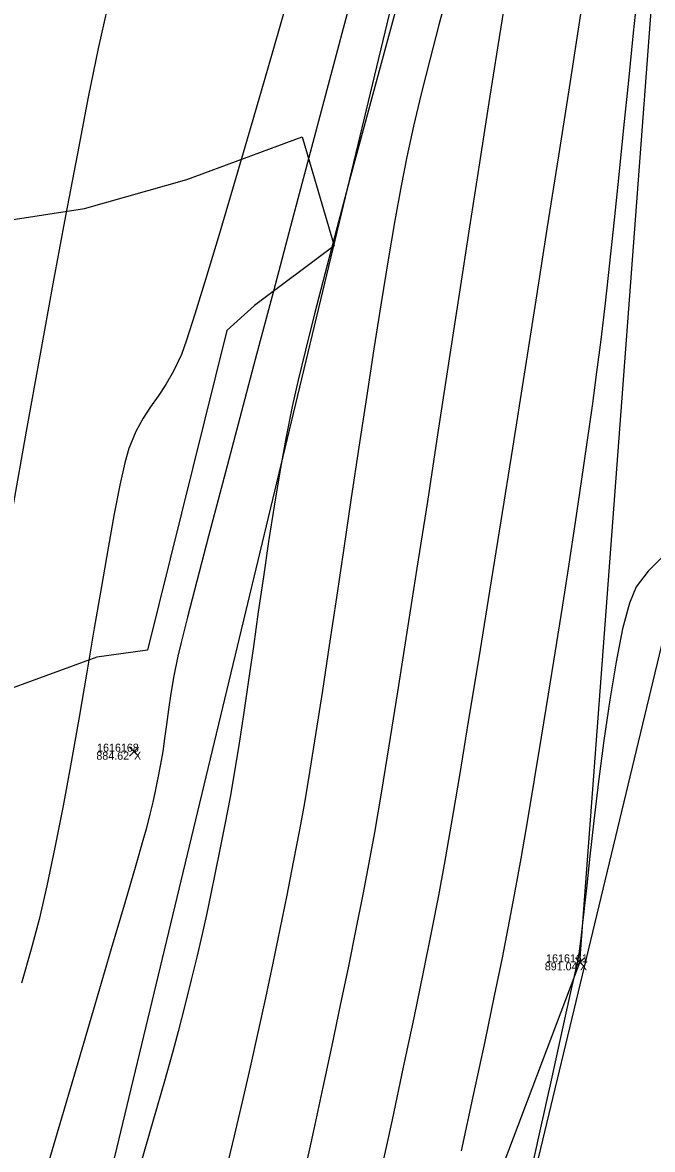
# Model space of a CAD drawing. Extents: x 1957117 to 1971063, y 701601 to 715861.
# Drawn here: x 1963262.79 to 1963290.32, y 705884.08 to 705933.37 of the extents above; entities that cross this region are included whole.
import ezdxf

# ---------------------------------------------------------------- set-up
doc = ezdxf.new("R2010")
doc.units = 0
for name, color, linetype in [('AP_X_Lights', 7, 'Continuous'), ('DT_X_Break_Line', 7, 'Continuous'), ('DT_X_Contour_Major', 7, 'Continuous'), ('DT_X_Contour_Minor', 7, 'Continuous'), ('GE_X_CL_20', 7, 'Continuous'), ('HY_X_Water_Edge', 7, 'Continuous'), ('PV_P_Shoulder', 7, 'Continuous'), ('RS_Raster1', 7, 'Continuous'), ('RW_X_Esmt_RR', 7, 'Continuous'), ('SC_Scratch1', 7, 'Continuous'), ('SC_Shading5', 7, 'Continuous'), ('VG_X_Tree_Line_Rt', 7, 'Continuous')]:
    doc.layers.add(name, color=color, linetype=linetype)

msp = doc.modelspace()

# ---------------------------------------------------------------- linework, layer by layer
at = {"layer": 'AP_X_Lights'}
for p, q in [((1963267.464, 705901.283), (1963267.852, 705901.673)), ((1963267.464, 705901.673), (1963267.852, 705901.283)), ((1963286.959, 705892.069), (1963287.347, 705892.459)), ((1963286.959, 705892.459), (1963287.347, 705892.069))]:
    msp.add_line(p, q, dxfattribs=at)
at = {"layer": 'DT_X_Break_Line'}
msp.add_lwpolyline([(1963248.355, 705747.376), (1963261.829, 705795.923), (1963267.581, 705840.559), (1963287.153, 705892.264), (1963291.083, 705944.763), (1963301.574, 705996.211), (1963311.528, 706039.027), (1963334.717, 706086.75), (1963331.957, 706106.508), (1963348.786, 706182.796), (1963365.664, 706223.934), (1963373.462, 706281.461), (1963387.853, 706330.217), (1963397.264, 706379.501), (1963407.696, 706427.592), (1963426.755, 706477.16), (1963442.136, 706524.014), (1963446.007, 706569.971), (1963489.391, 706666.839), (1963500.526, 706701.536)], dxfattribs=at)
at = {"layer": 'DT_X_Contour_Major'}
for points in [[(1963289.692, 705934.967), (1963289.482, 705932.914), (1963289.271, 705930.834), (1963289.062, 705928.756), (1963288.854, 705926.712), (1963288.649, 705924.732), (1963288.449, 705922.847), (1963288.253, 705921.089), (1963288.064, 705919.486), (1963287.882, 705918.071), (1963287.679, 705916.598), (1963287.452, 705915.001), (1963287.205, 705913.302), (1963286.941, 705911.52), (1963286.662, 705909.677), (1963286.372, 705907.794), (1963286.073, 705905.89), (1963285.769, 705903.988), (1963285.463, 705902.107), (1963285.157, 705900.269), (1963284.856, 705898.493), (1963284.561, 705896.801), (1963284.276, 705895.214), (1963284.004, 705893.753), (1963283.749, 705892.463), (1963283.407, 705890.796), (1963282.987, 705888.799), (1963282.501, 705886.525), (1963281.961, 705884.024)], [(1963289.692, 705934.967), (1963289.482, 705932.914), (1963289.271, 705930.834), (1963289.062, 705928.756), (1963288.854, 705926.712), (1963288.649, 705924.732), (1963288.449, 705922.847), (1963288.253, 705921.089), (1963288.064, 705919.486), (1963287.882, 705918.071), (1963287.679, 705916.598), (1963287.452, 705915.001), (1963287.205, 705913.302), (1963286.941, 705911.52), (1963286.662, 705909.677), (1963286.372, 705907.794), (1963286.073, 705905.89), (1963285.769, 705903.988), (1963285.463, 705902.107), (1963285.157, 705900.269), (1963284.856, 705898.493), (1963284.561, 705896.801), (1963284.276, 705895.214), (1963284.004, 705893.753), (1963283.749, 705892.463), (1963283.407, 705890.796), (1963282.987, 705888.799), (1963282.501, 705886.525), (1963281.961, 705884.024)], [(1963277.092, 705934.198), (1963276.263, 705931.077), (1963275.421, 705927.903), (1963274.579, 705924.731), (1963273.753, 705921.62), (1963272.958, 705918.624), (1963272.211, 705915.801), (1963271.526, 705913.208), (1963270.918, 705910.899), (1963270.404, 705908.933), (1963269.997, 705907.365), (1963269.715, 705906.252), (1963269.571, 705905.65), (1963269.404, 705904.802), (1963269.273, 705904.028), (1963269.167, 705903.32), (1963269.078, 705902.666), (1963268.996, 705902.056), (1963268.913, 705901.481), (1963268.818, 705900.93), (1963268.691, 705900.269), (1963268.586, 705899.745), (1963268.481, 705899.268), (1963268.357, 705898.748), (1963268.191, 705898.096), (1963268.05, 705897.597), (1963267.737, 705896.516), (1963267.269, 705894.915), (1963266.665, 705892.857), (1963265.944, 705890.404), (1963265.125, 705887.618), (1963264.225, 705884.563), (1963263.263, 705881.3)], [(1963277.092, 705934.198), (1963276.263, 705931.077), (1963275.421, 705927.903), (1963274.579, 705924.731), (1963273.753, 705921.62), (1963272.958, 705918.624), (1963272.211, 705915.801), (1963271.526, 705913.208), (1963270.918, 705910.899), (1963270.404, 705908.933), (1963269.997, 705907.365), (1963269.715, 705906.252), (1963269.571, 705905.65), (1963269.404, 705904.802), (1963269.273, 705904.028), (1963269.167, 705903.32), (1963269.078, 705902.666), (1963268.996, 705902.056), (1963268.913, 705901.481), (1963268.818, 705900.93), (1963268.691, 705900.269), (1963268.586, 705899.745), (1963268.481, 705899.268), (1963268.357, 705898.748), (1963268.191, 705898.096), (1963268.05, 705897.597), (1963267.737, 705896.516), (1963267.269, 705894.915), (1963266.665, 705892.857), (1963265.944, 705890.404), (1963265.125, 705887.618), (1963264.225, 705884.563), (1963263.263, 705881.3)]]:
    msp.add_lwpolyline(points, dxfattribs=at)
at = {"layer": 'DT_X_Contour_Minor'}
for points in [[(1963287.494, 705935.797), (1963287.104, 705933.274), (1963286.674, 705930.505), (1963286.212, 705927.542), (1963285.726, 705924.433), (1963285.223, 705921.231), (1963284.712, 705917.986), (1963284.199, 705914.749), (1963283.692, 705911.569), (1963283.2, 705908.498), (1963282.729, 705905.586), (1963282.287, 705902.884), (1963281.883, 705900.443), (1963281.522, 705898.313), (1963281.215, 705896.544), (1963280.966, 705895.188), (1963280.664, 705893.637), (1963280.301, 705891.842), (1963279.887, 705889.842), (1963279.431, 705887.676), (1963278.94, 705885.381), (1963278.423, 705882.996)], [(1963287.494, 705935.797), (1963287.104, 705933.274), (1963286.674, 705930.505), (1963286.212, 705927.542), (1963285.726, 705924.433), (1963285.223, 705921.231), (1963284.712, 705917.986), (1963284.199, 705914.749), (1963283.692, 705911.569), (1963283.2, 705908.498), (1963282.729, 705905.586), (1963282.287, 705902.884), (1963281.883, 705900.443), (1963281.522, 705898.313), (1963281.215, 705896.544), (1963280.966, 705895.188), (1963280.664, 705893.637), (1963280.301, 705891.842), (1963279.887, 705889.842), (1963279.431, 705887.676), (1963278.94, 705885.381), (1963278.423, 705882.996)], [(1963279.535, 705935.557), (1963278.908, 705933.245), (1963278.285, 705930.94), (1963277.673, 705928.672), (1963277.085, 705926.475), (1963276.528, 705924.38), (1963276.014, 705922.419), (1963275.552, 705920.626), (1963275.152, 705919.032), (1963274.825, 705917.669), (1963274.579, 705916.57), (1963274.301, 705915.177), (1963274.037, 705913.719), (1963273.785, 705912.213), (1963273.544, 705910.678), (1963273.314, 705909.131), (1963273.091, 705907.591), (1963272.876, 705906.076), (1963272.666, 705904.603), (1963272.461, 705903.19), (1963272.258, 705901.856), (1963272.057, 705900.618), (1963271.855, 705899.494), (1963271.625, 705898.289), (1963271.413, 705897.2), (1963271.213, 705896.199), (1963271.018, 705895.257), (1963270.822, 705894.345), (1963270.618, 705893.435), (1963270.399, 705892.498), (1963270.158, 705891.506), (1963269.89, 705890.43), (1963269.587, 705889.241), (1963269.349, 705888.359), (1963268.985, 705887.066), (1963268.509, 705885.408), (1963267.935, 705883.433)], [(1963279.535, 705935.557), (1963278.908, 705933.245), (1963278.285, 705930.94), (1963277.673, 705928.672), (1963277.085, 705926.475), (1963276.528, 705924.38), (1963276.014, 705922.419), (1963275.552, 705920.626), (1963275.152, 705919.032), (1963274.825, 705917.669), (1963274.579, 705916.57), (1963274.301, 705915.177), (1963274.037, 705913.719), (1963273.785, 705912.213), (1963273.544, 705910.678), (1963273.314, 705909.131), (1963273.091, 705907.591), (1963272.876, 705906.076), (1963272.666, 705904.603), (1963272.461, 705903.19), (1963272.258, 705901.856), (1963272.057, 705900.618), (1963271.855, 705899.494), (1963271.625, 705898.289), (1963271.413, 705897.2), (1963271.213, 705896.199), (1963271.018, 705895.257), (1963270.822, 705894.345), (1963270.618, 705893.435), (1963270.399, 705892.498), (1963270.158, 705891.506), (1963269.89, 705890.43), (1963269.587, 705889.241), (1963269.349, 705888.359), (1963268.985, 705887.066), (1963268.509, 705885.408), (1963267.935, 705883.433)], [(1963281.399, 705934.836), (1963280.982, 705933.268), (1963280.587, 705931.736), (1963280.218, 705930.255), (1963279.883, 705928.835), (1963279.587, 705927.491), (1963279.334, 705926.219), (1963279.06, 705924.709), (1963278.768, 705922.994), (1963278.462, 705921.11), (1963278.143, 705919.092), (1963277.818, 705916.975), (1963277.487, 705914.794), (1963277.156, 705912.584), (1963276.828, 705910.379), (1963276.505, 705908.216), (1963276.192, 705906.129), (1963275.893, 705904.152), (1963275.609, 705902.322), (1963275.346, 705900.673), (1963275.106, 705899.24), (1963274.892, 705898.059), (1963274.62, 705896.646), (1963274.333, 705895.197), (1963274.033, 705893.72), (1963273.722, 705892.222), (1963273.4, 705890.71), (1963273.07, 705889.193), (1963272.732, 705887.677), (1963272.389, 705886.171), (1963272.04, 705884.681), (1963271.689, 705883.215)], [(1963281.399, 705934.836), (1963280.982, 705933.268), (1963280.587, 705931.736), (1963280.218, 705930.255), (1963279.883, 705928.835), (1963279.587, 705927.491), (1963279.334, 705926.219), (1963279.06, 705924.709), (1963278.768, 705922.994), (1963278.462, 705921.11), (1963278.143, 705919.092), (1963277.818, 705916.975), (1963277.487, 705914.794), (1963277.156, 705912.584), (1963276.828, 705910.379), (1963276.505, 705908.216), (1963276.192, 705906.129), (1963275.893, 705904.152), (1963275.609, 705902.322), (1963275.346, 705900.673), (1963275.106, 705899.24), (1963274.892, 705898.059), (1963274.62, 705896.646), (1963274.333, 705895.197), (1963274.033, 705893.72), (1963273.722, 705892.222), (1963273.4, 705890.71), (1963273.07, 705889.193), (1963272.732, 705887.677), (1963272.389, 705886.171), (1963272.04, 705884.681), (1963271.689, 705883.215)], [(1963283.89, 705934.359), (1963283.552, 705932.255), (1963283.174, 705929.864), (1963282.764, 705927.237), (1963282.33, 705924.428), (1963281.876, 705921.49), (1963281.413, 705918.475), (1963280.945, 705915.436), (1963280.481, 705912.427), (1963280.027, 705909.5), (1963279.591, 705906.707), (1963279.18, 705904.103), (1963278.802, 705901.74), (1963278.462, 705899.67), (1963278.169, 705897.947), (1963277.929, 705896.623), (1963277.66, 705895.229), (1963277.358, 705893.712), (1963277.029, 705892.093), (1963276.676, 705890.39), (1963276.303, 705888.622), (1963275.915, 705886.808), (1963275.515, 705884.967), (1963275.107, 705883.118)], [(1963283.89, 705934.359), (1963283.552, 705932.255), (1963283.174, 705929.864), (1963282.764, 705927.237), (1963282.33, 705924.428), (1963281.876, 705921.49), (1963281.413, 705918.475), (1963280.945, 705915.436), (1963280.481, 705912.427), (1963280.027, 705909.5), (1963279.591, 705906.707), (1963279.18, 705904.103), (1963278.802, 705901.74), (1963278.462, 705899.67), (1963278.169, 705897.947), (1963277.929, 705896.623), (1963277.66, 705895.229), (1963277.358, 705893.712), (1963277.029, 705892.093), (1963276.676, 705890.39), (1963276.303, 705888.622), (1963275.915, 705886.808), (1963275.515, 705884.967), (1963275.107, 705883.118)], [(1963266.479, 705933.988), (1963266.096, 705932.231), (1963265.661, 705930.1), (1963265.181, 705927.644), (1963264.663, 705924.908), (1963264.113, 705921.939), (1963263.538, 705918.785), (1963262.945, 705915.492), (1963262.34, 705912.108), (1963261.73, 705908.679), (1963261.12, 705905.252), (1963260.519, 705901.874), (1963259.933, 705898.592), (1963259.367, 705895.454), (1963258.829, 705892.505), (1963258.326, 705889.793), (1963257.863, 705887.366), (1963257.448, 705885.269), (1963257.088, 705883.549)], [(1963266.479, 705933.988), (1963266.096, 705932.231), (1963265.661, 705930.1), (1963265.181, 705927.644), (1963264.663, 705924.908), (1963264.113, 705921.939), (1963263.538, 705918.785), (1963262.945, 705915.492), (1963262.34, 705912.108), (1963261.73, 705908.679), (1963261.12, 705905.252), (1963260.519, 705901.874), (1963259.933, 705898.592), (1963259.367, 705895.454), (1963258.829, 705892.505), (1963258.326, 705889.793), (1963257.863, 705887.366), (1963257.448, 705885.269), (1963257.088, 705883.549)], [(1963274.284, 705934.061), (1963273.51, 705931.371), (1963272.755, 705928.769), (1963272.039, 705926.322), (1963271.381, 705924.101), (1963270.802, 705922.173), (1963270.321, 705920.608), (1963269.957, 705919.475), (1963269.732, 705918.843), (1963269.39, 705918.114), (1963269.05, 705917.53), (1963268.714, 705917.033), (1963268.382, 705916.564), (1963268.057, 705916.064), (1963267.739, 705915.475), (1963267.431, 705914.738), (1963267.251, 705914.107), (1963267.037, 705913.14), (1963266.794, 705911.885), (1963266.524, 705910.392), (1963266.232, 705908.707), (1963265.921, 705906.88), (1963265.595, 705904.957), (1963265.256, 705902.989), (1963264.909, 705901.022), (1963264.557, 705899.105), (1963264.204, 705897.286), (1963263.852, 705895.614), (1963263.506, 705894.136), (1963263.165, 705892.843), (1963262.743, 705891.35)], [(1963274.284, 705934.061), (1963273.51, 705931.371), (1963272.755, 705928.769), (1963272.039, 705926.322), (1963271.381, 705924.101), (1963270.802, 705922.173), (1963270.321, 705920.608), (1963269.957, 705919.475), (1963269.732, 705918.843), (1963269.39, 705918.114), (1963269.05, 705917.53), (1963268.714, 705917.033), (1963268.382, 705916.564), (1963268.057, 705916.064), (1963267.739, 705915.475), (1963267.431, 705914.738), (1963267.251, 705914.107), (1963267.037, 705913.14), (1963266.794, 705911.885), (1963266.524, 705910.392), (1963266.232, 705908.707), (1963265.921, 705906.88), (1963265.595, 705904.957), (1963265.256, 705902.989), (1963264.909, 705901.022), (1963264.557, 705899.105), (1963264.204, 705897.286), (1963263.852, 705895.614), (1963263.506, 705894.136), (1963263.165, 705892.843), (1963262.743, 705891.35)], [(1963290.733, 705909.978), (1963290.132, 705909.379), (1963289.612, 705908.69), (1963289.314, 705907.981), (1963289.018, 705906.855), (1963288.73, 705905.412), (1963288.455, 705903.75), (1963288.197, 705901.969), (1963287.963, 705900.169), (1963287.756, 705898.447), (1963287.582, 705896.905), (1963287.446, 705895.64), (1963287.353, 705894.752), (1963287.309, 705894.342), (1963287.266, 705893.999), (1963287.237, 705893.716), (1963287.212, 705893.457), (1963287.179, 705893.185), (1963287.136, 705892.873), (1963287.097, 705892.626), (1963287.041, 705892.317), (1963286.955, 705891.922), (1963286.73, 705890.899), (1963286.381, 705889.318), (1963285.924, 705887.249), (1963285.374, 705884.763), (1963284.747, 705881.928)], [(1963290.733, 705909.978), (1963290.132, 705909.379), (1963289.612, 705908.69), (1963289.314, 705907.981), (1963289.018, 705906.855), (1963288.73, 705905.412), (1963288.455, 705903.75), (1963288.197, 705901.969), (1963287.963, 705900.169), (1963287.756, 705898.447), (1963287.582, 705896.905), (1963287.446, 705895.64), (1963287.353, 705894.752), (1963287.309, 705894.342), (1963287.266, 705893.999), (1963287.237, 705893.716), (1963287.212, 705893.457), (1963287.179, 705893.185), (1963287.136, 705892.873), (1963287.097, 705892.626), (1963287.041, 705892.317), (1963286.955, 705891.922), (1963286.73, 705890.899), (1963286.381, 705889.318), (1963285.924, 705887.249), (1963285.374, 705884.763), (1963284.747, 705881.928)]]:
    msp.add_lwpolyline(points, dxfattribs=at)
at = {"layer": 'GE_X_CL_20'}
msp.add_lwpolyline([(1963418.3, 706437.397), (1962895.621, 704261.062)], dxfattribs=at)
at = {"layer": 'HY_X_Water_Edge'}
msp.add_spline([(1963191.723, 701994.048), (1963062.047, 702441.167), (1962863.491, 703169.356), (1962827.53, 703438.691), (1962823.213, 703537.412), (1962817.962, 703593.874), (1962817.97, 703697.316), (1962828.582, 703804.235), (1962836.461, 703844.734), (1962850.687, 703896.004), (1962867.251, 703938.846), (1962873.848, 703992.355), (1962884.135, 704091.371), (1962891.241, 704140.854), (1962897.382, 704180.529), (1962905.467, 704230.979), (1962943.949, 704328.022), (1962948.537, 704378.842), (1962964.114, 704426.264), (1963004.885, 704570.73), (1963042.054, 704716.522), (1963062.038, 704814.417), (1963072.171, 704860.237), (1963090.023, 704956.798), (1963107.066, 705031.783), (1963133.773, 705105.742), (1963148.685, 705206.74), (1963175.48, 705301.059), (1963191.635, 705353.417), (1963210.988, 705447.286), (1963219.532, 705497.27), (1963230.124, 705549.475), (1963251.052, 705591.159), (1963275.289, 705693.429), (1963292.982, 705784.032), (1963302.841, 705839.645), (1963335.126, 705936.766), (1963359.752, 706046.75), (1963389.133, 706177.299), (1963417.827, 706273.456), (1963475.868, 706451.902), (1963533.782, 706640.53), (1963553.86, 706696.984), (1963580.184, 706715.425), (1963609.172, 706718.73), (1963617.062, 706714.691), (1963619.447, 706694.678), (1963564.282, 706533.07), (1963531.853, 706395.229), (1963434.4, 706006.96), (1963354.09, 705679.186), (1963237.513, 705206.07), (1963167.369, 704892.962), (1963059.145, 704434.176), (1962907.914, 703908.742), (1962877.458, 703703.326), (1962898.357, 703412.121), (1962942.65, 703052.267), (1963048.963, 702674.866), (1963191.468, 702189.666), (1963245.396, 702019.832)], degree=3, dxfattribs=at)
at = {"layer": 'RW_X_Esmt_RR'}
msp.add_lwpolyline([(1962866.45, 704268.068), (1963123.345, 705337.727), (1963135.496, 705336.937), (1963400.797, 706441.601)], dxfattribs=at)
at = {"layer": 'SC_Shading5'}
for points in [[(1963026.912, 704294.121), (1963138.818, 704737.794), (1963251.679, 705213.963), (1963374.306, 705730.111), (1963454.783, 706045.593), (1963517.244, 706296.713), (1963562.763, 706479.256), (1963580.13, 706553.799), (1963589.678, 706586.994)], [(1963609.915, 706579.703), (1963587.283, 706499.153), (1963552.056, 706354.005), (1963480.911, 706069.234), (1963357.401, 705576.869), (1963272.751, 705226.931), (1963210.247, 704956.481), (1963044.97, 704288.881)]]:
    msp.add_spline(points, degree=3, dxfattribs=at)
at = {"layer": 'VG_X_Tree_Line_Rt'}
msp.add_lwpolyline([(1963255.977, 705934.363), (1963258.391, 705927.721), (1963260.677, 705924.495), (1963265.488, 705925.234), (1963269.974, 705926.508), (1963275.009, 705928.369), (1963276.406, 705923.595), (1963272.923, 705920.999), (1963271.71, 705919.905), (1963268.255, 705905.913), (1963268.255, 705905.913), (1963266.029, 705905.605), (1963261.559, 705903.979), (1963257.58, 705900.767), (1963252.673, 705898.457), (1963245.929, 705894.771), (1963245.656, 705887.225), (1963242.747, 705883.607)], dxfattribs=at)

# ---------------------------------------------------------------- texts
at = {"layer": 'PV_P_Shoulder'}
for s, p in [('884.62', (1963266.013, 705901.128)), ('891.04', (1963285.615, 705891.914))]:
    msp.add_text(s, height=0.35, dxfattribs=at).set_placement(p)
at = {"layer": 'RS_Raster1'}
for s, p in [('1616168', (1963266.044, 705901.478)), ('1616161', (1963285.673, 705892.264))]:
    msp.add_text(s, height=0.35, dxfattribs=at).set_placement(p)
at = {"layer": 'SC_Scratch1'}
for p in [(1963267.658, 705901.128), (1963287.153, 705891.914)]:
    msp.add_text('X', height=0.35, dxfattribs=at).set_placement(p)

doc.saveas('drawing.dxf')
